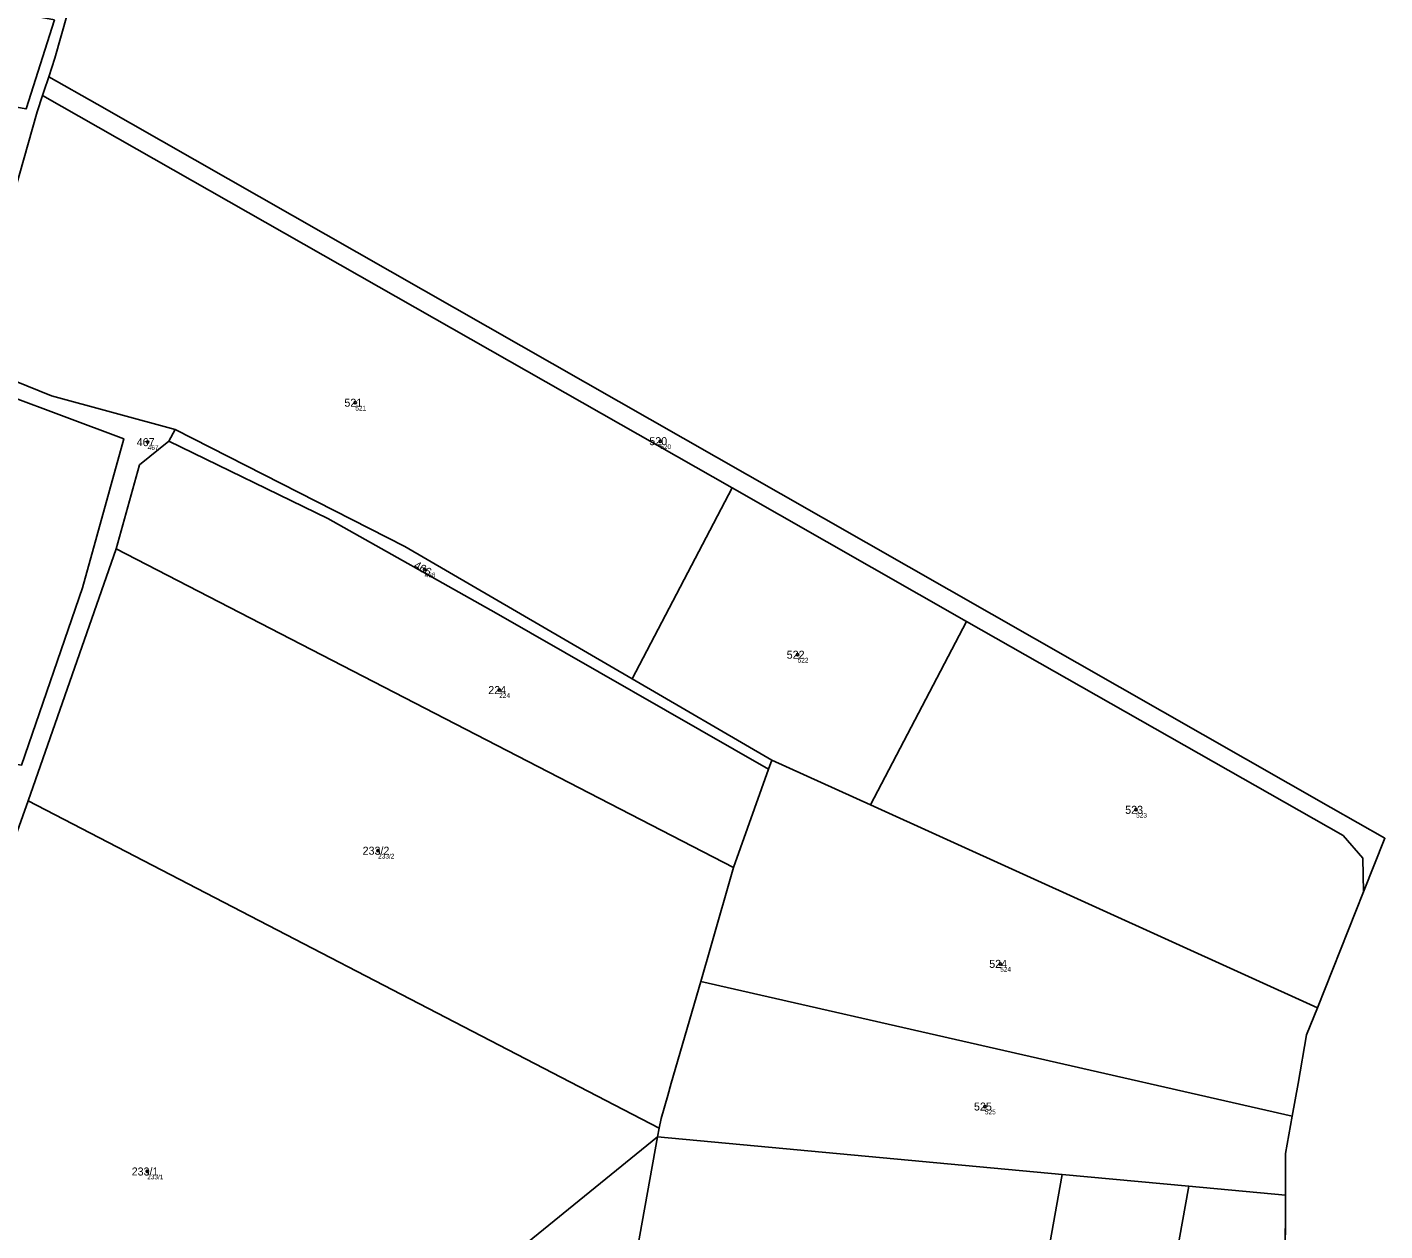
# Model space of a CAD drawing. Extents: x -700238 to -698499, y -1070626 to -1068006.
# Drawn here: x -699139.8 to -698851.3, y -1069166.6 to -1068910.8 of the extents above; entities that cross this region are included whole.
import ezdxf

# ---------------------------------------------------------------- set-up
doc = ezdxf.new("R2010")
doc.units = 0
for name, color, linetype in [('Definiční body', 7, 'Continuous'), ('Hranice parcel', 7, 'Continuous'), ('Parcelní čísla', 7, 'Continuous'), ('Polygon ku', 7, 'Continuous'), ('Polygon parcely', 7, 'Continuous')]:
    doc.layers.add(name, color=color, linetype=linetype)

msp = doc.modelspace()

# ---------------------------------------------------------------- linework, layer by layer
at = {"layer": 'Definiční body'}
for centre in [(-699070.06, -1068990.61994), (-699114.18, -1068998.99994), (-699005.27, -1068998.78994), (-699055.34, -1069026.04994), (-698976.08, -1069044.15994), (-699039.49, -1069051.66994), (-698904.17, -1069077.10994), (-699065.21, -1069085.79994), (-698933.05, -1069109.83994), (-698936.29, -1069140.14994), (-699114.28, -1069153.94994)]:
    msp.add_circle(centre, 0.25, dxfattribs=at)
at = {"layer": 'Hranice parcel'}
for p, q in [((-699140.02, -1068928.19), (-699133.96, -1068909.29)), ((-699135.17, -1068921.35), (-699124.92, -1068927.2)), ((-698990.02, -1069008.7), (-699136.49, -1068925.34)), ((-699108.35, -1068996.32), (-699109.67, -1068998.78)), ((-699011.24, -1069049.26), (-698990.02, -1069008.7)), ((-698940.19, -1069037.07), (-698990.02, -1069008.7)), ((-699120.84, -1069021.69), (-699139.55, -1069075.18)), ((-699120.84, -1069021.69), (-698989.7, -1069089.38)), ((-698960.57, -1069076.08), (-698940.19, -1069037.07)), ((-698981.54, -1069066.54), (-699011.24, -1069049.26)), ((-698989.7, -1069089.38), (-698982.24, -1069068.49)), ((-698982.24, -1069068.49), (-698981.54, -1069066.54)), ((-698981.54, -1069066.54), (-698960.57, -1069076.08)), ((-699005.49, -1069144.75), (-699139.55, -1069075.18)), ((-698960.57, -1069076.08), (-698865.65, -1069119.19)), ((-698851.32, -1069083.16), (-698855.84, -1069094.53)), ((-698855.84, -1069094.53), (-698865.65, -1069119.19)), ((-698871.01, -1069142.19), (-698996.68, -1069113.57)), ((-698869.77, -1069135.22), (-698871.01, -1069142.19)), ((-699005.09, -1069142.68), (-699005.49, -1069144.75)), ((-699005.49, -1069144.75), (-699005.85, -1069146.6)), ((-699033.5, -1069169.01), (-699005.85, -1069146.6)), ((-699005.85, -1069146.6), (-698919.85, -1069154.59)), ((-698919.85, -1069154.59), (-698892.97, -1069157.09)), ((-698892.97, -1069157.09), (-698872.46, -1069159)), ((-698872.46, -1069159), (-698872.58, -1069192.79))]:
    msp.add_line(p, q, dxfattribs=at)
for points in [[(-699120.47, -1068869.91), (-699133.87, -1068917.39), (-699135.17, -1068921.35)], [(-699136.49, -1068925.34), (-699136.22, -1068924.52), (-699135.17, -1068921.35)], [(-699136.49, -1068925.34), (-699137.63, -1068928.8), (-699143.34, -1068948.89), (-699148.15, -1068966.39), (-699153.04, -1068981.73), (-699134.62, -1068989.13), (-699108.35, -1068996.32)], [(-699124.92, -1068927.2), (-698979.66, -1069010), (-698862.77, -1069076.63), (-698851.32, -1069083.16)], [(-699141, -1069067.64), (-699128.02, -1069029.95), (-699119.24, -1068998.27), (-699156.76, -1068984.27), (-699151.24, -1068965.73)], [(-699108.35, -1068996.32), (-699059.55, -1069021.15), (-699011.24, -1069049.26)], [(-699109.67, -1068998.78), (-699115.89, -1069003.84), (-699120.84, -1069021.69)], [(-698982.24, -1069068.49), (-699040.1, -1069035.32), (-699075.92, -1069015.19), (-699109.67, -1068998.78)], [(-698855.84, -1069094.53), (-698856.01, -1069087.36), (-698860.2, -1069082.59), (-698940.19, -1069037.07)], [(-699139.55, -1069075.18), (-699174.33, -1069172.85), (-699190.29, -1069222.45), (-699200.68, -1069246.54)], [(-698996.68, -1069113.57), (-698994.49, -1069105.96), (-698989.7, -1069089.38)], [(-698996.68, -1069113.57), (-699002.93, -1069135.2), (-699003.67, -1069137.77), (-699005.09, -1069142.68)], [(-698865.65, -1069119.19), (-698867.94, -1069124.95), (-698869.77, -1069135.22)], [(-698871.01, -1069142.19), (-698872.43, -1069150.13), (-698872.46, -1069159)], [(-699042.33, -1069338.18), (-699016.12, -1069203.76), (-699005.85, -1069146.6)], [(-698958.13, -1069368.71), (-698938.42, -1069258.47), (-698919.85, -1069154.59)], [(-698932.44, -1069376.34), (-698913.07, -1069268.73), (-698892.97, -1069157.09)]]:
    msp.add_lwpolyline(points, dxfattribs=at)
at = {"layer": 'Polygon ku'}
msp.add_lwpolyline([(-698872.58, -1069192.79), (-698872.46, -1069159), (-698872.43, -1069150.13), (-698871.01, -1069142.19), (-698869.77, -1069135.22), (-698867.94, -1069124.95), (-698865.65, -1069119.19), (-698855.84, -1069094.53), (-698851.32, -1069083.16), (-698862.77, -1069076.63), (-698979.66, -1069010), (-699124.92, -1068927.2), (-699135.17, -1068921.35), (-699133.87, -1068917.39), (-699120.47, -1068869.91)], dxfattribs=at)
at = {"layer": 'Polygon parcely'}
for points in [[(-699143.34, -1068948.89), (-699137.63, -1068928.8), (-699136.49, -1068925.34), (-699136.22, -1068924.52), (-699135.17, -1068921.35), (-699133.87, -1068917.39), (-699120.47, -1068869.91)], [(-699133.96, -1068909.29), (-699140.02, -1068928.19)], [(-699174.33, -1069172.85), (-699139.55, -1069075.18), (-699120.84, -1069021.69), (-699115.89, -1069003.84), (-699109.67, -1068998.78), (-699108.35, -1068996.32), (-699134.62, -1068989.13), (-699153.04, -1068981.73)], [(-699156.76, -1068984.27), (-699119.24, -1068998.27), (-699128.02, -1069029.95), (-699141, -1069067.64)]]:
    msp.add_lwpolyline(points, dxfattribs=at)
for points in [[(-699133.96, -1068909.29), (-699178.12, -1068901.11), (-699223.74, -1068894.86), (-699345.65, -1068879.11), (-699347.13, -1068893.81), (-699242.99, -1068910.5), (-699140.02, -1068928.19)], [(-698862.77, -1069076.63), (-698979.66, -1069010), (-699124.92, -1068927.2), (-699135.17, -1068921.35), (-699136.22, -1068924.52), (-699136.49, -1068925.34), (-698990.02, -1069008.7), (-698940.19, -1069037.07), (-698860.2, -1069082.59), (-698856.01, -1069087.36), (-698855.84, -1069094.53), (-698851.32, -1069083.16)], [(-699153.04, -1068981.73), (-699134.62, -1068989.13), (-699108.35, -1068996.32), (-699059.55, -1069021.15), (-699011.24, -1069049.26), (-698990.02, -1069008.7), (-699136.49, -1068925.34), (-699137.63, -1068928.8), (-699143.34, -1068948.89), (-699148.15, -1068966.39)], [(-699417.2, -1069022.3), (-699305.17, -1069040.57), (-699141, -1069067.64), (-699128.02, -1069029.95), (-699119.24, -1068998.27), (-699156.76, -1068984.27), (-699151.24, -1068965.73), (-699205.87, -1068953.7), (-699289.3, -1068939.86), (-699351.16, -1068930.36), (-699361.06, -1068949.46), (-699389.97, -1068984.13), (-699400.27, -1068995.84), (-699406.14, -1069005.3)], [(-698981.54, -1069066.54), (-699011.24, -1069049.26), (-699059.55, -1069021.15), (-699108.35, -1068996.32), (-699109.67, -1068998.78), (-699075.92, -1069015.19), (-699040.1, -1069035.32), (-698982.24, -1069068.49)], [(-698982.24, -1069068.49), (-699040.1, -1069035.32), (-699075.92, -1069015.19), (-699109.67, -1068998.78), (-699115.89, -1069003.84), (-699120.84, -1069021.69), (-698989.7, -1069089.38)], [(-698960.57, -1069076.08), (-698940.19, -1069037.07), (-698990.02, -1069008.7), (-699011.24, -1069049.26), (-698981.54, -1069066.54)], [(-698989.7, -1069089.38), (-699120.84, -1069021.69), (-699139.55, -1069075.18), (-699005.49, -1069144.75), (-699005.09, -1069142.68), (-699003.67, -1069137.77), (-699002.93, -1069135.2), (-698996.68, -1069113.57), (-698994.49, -1069105.96)], [(-698855.84, -1069094.53), (-698856.01, -1069087.36), (-698860.2, -1069082.59), (-698940.19, -1069037.07), (-698960.57, -1069076.08), (-698865.65, -1069119.19)], [(-698869.77, -1069135.22), (-698867.94, -1069124.95), (-698865.65, -1069119.19), (-698960.57, -1069076.08), (-698981.54, -1069066.54), (-698982.24, -1069068.49), (-698989.7, -1069089.38), (-698994.49, -1069105.96), (-698996.68, -1069113.57), (-698871.01, -1069142.19)], [(-699200.68, -1069246.54), (-699188.36, -1069250.3), (-699115.53, -1069211.13), (-699068.5, -1069188.78), (-699033.5, -1069169.01), (-699005.85, -1069146.6), (-699005.49, -1069144.75), (-699139.55, -1069075.18), (-699174.33, -1069172.85), (-699190.29, -1069222.45)], [(-698996.68, -1069113.57), (-699002.93, -1069135.2), (-699003.67, -1069137.77), (-699005.09, -1069142.68), (-699005.49, -1069144.75), (-699005.85, -1069146.6), (-698919.85, -1069154.59), (-698892.97, -1069157.09), (-698872.46, -1069159), (-698872.43, -1069150.13), (-698871.01, -1069142.19)], [(-699016.12, -1069203.76), (-699005.85, -1069146.6), (-699033.5, -1069169.01), (-699064.45, -1069326.3), (-699042.33, -1069338.18)], [(-698938.42, -1069258.47), (-698919.85, -1069154.59), (-699005.85, -1069146.6), (-699016.12, -1069203.76), (-699042.33, -1069338.18), (-699032.57, -1069343.13), (-698958.13, -1069368.71)], [(-698932.44, -1069376.34), (-698913.07, -1069268.73), (-698892.97, -1069157.09), (-698919.85, -1069154.59), (-698938.42, -1069258.47), (-698958.13, -1069368.71)], [(-698907.48, -1069383.06), (-698872.58, -1069192.79), (-698872.46, -1069159), (-698892.97, -1069157.09), (-698913.07, -1069268.73), (-698932.44, -1069376.34)]]:
    msp.add_lwpolyline(points, close=True, dxfattribs=at)

# ---------------------------------------------------------------- texts
at = {"layer": 'Definiční body'}
for s, p in [('521', (-699070.06, -1068992.276)), ('467', (-699114.18, -1069000.656)), ('520', (-699005.27, -1069000.446)), ('466', (-699055.34, -1069027.706)), ('522', (-698976.08, -1069045.816)), ('224', (-699039.49, -1069053.326)), ('523', (-698904.17, -1069078.766)), ('233/2', (-699065.21, -1069087.456)), ('524', (-698933.05, -1069111.496)), ('525', (-698936.29, -1069141.806)), ('233/1', (-699114.28, -1069155.606))]:
    msp.add_text(s, height=0.999996, dxfattribs=at).set_placement(p)
at = {"layer": 'Parcelní čísla'}
for s, p in [('521', (-699072.385, -1068991.47)), ('467', (-699116.505, -1068999.85)), ('520', (-699007.595, -1068999.64)), ('522', (-698978.405, -1069045.009)), ('224', (-699041.815, -1069052.519)), ('523', (-698906.495, -1069077.96)), ('233/2', (-699068.508, -1069086.65)), ('524', (-698935.375, -1069110.69)), ('525', (-698938.615, -1069140.999)), ('233/1', (-699117.578, -1069154.8))]:
    msp.add_text(s, height=1.699998, dxfattribs=at).set_placement(p)
msp.add_text('466', height=1.699998, rotation=329.9999972, dxfattribs=at).set_placement((-699057.778, -1069025.623))

doc.saveas('drawing.dxf')
